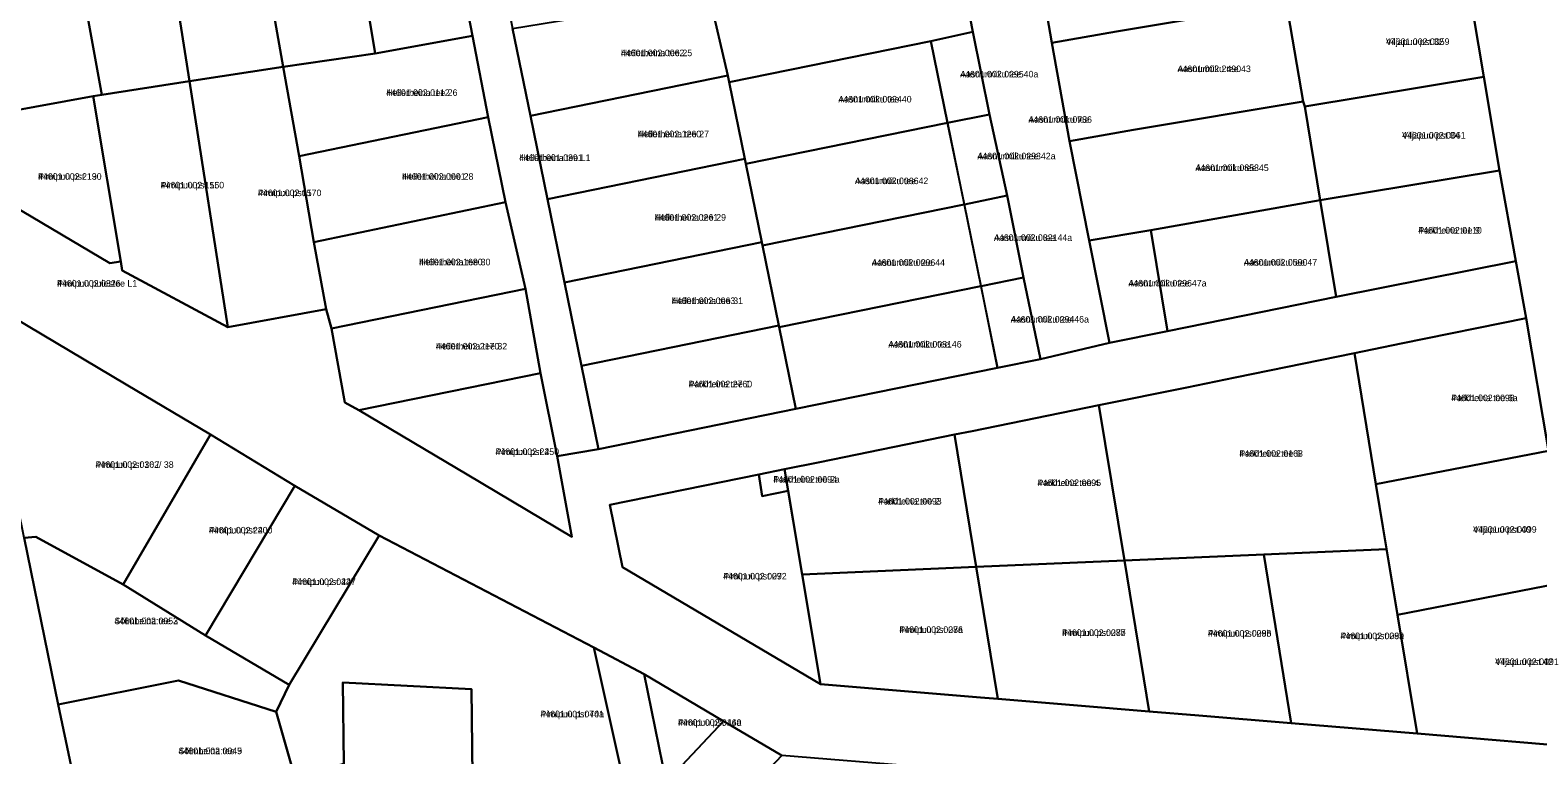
# Model space of a CAD drawing. Extents: x 551843 to 558501, y 6589003 to 6595718.
# Drawn here: x 552845.1 to 553189.3, y 6593581.9 to 6593747.5 of the extents above; entities that cross this region are included whole.
import ezdxf

# ---------------------------------------------------------------- set-up
doc = ezdxf.new("R2010")
doc.units = 0
for name, color, linetype in [('L_AADRESS', 7, 'Continuous'), ('PIIR', 7, 'Continuous'), ('TUNNUS', 7, 'Continuous')]:
    doc.layers.add(name, color=color, linetype=linetype)

msp = doc.modelspace()

# ---------------------------------------------------------------- linework, layer by layer
at = {"layer": 'PIIR'}
for points in [[(553191.73, 6593651.42), (553186.62, 6593681.71), (553184.25, 6593694.72), (553180.55, 6593715.48), (553176.97, 6593736.83), (553173.4, 6593758.18), (553169.77, 6593779.51), (553166.09, 6593800.76), (553162.42, 6593822.28), (553160.89, 6593831), (553157.49, 6593851.43), (553154.18, 6593871.61), (553150.68, 6593891.44), (553147.39, 6593911.24), (553144.11, 6593930.87), (553140.81, 6593950.3)], [(552821.1, 6593719.29), (552863.28, 6593694.26), (552865.76, 6593694.68), (552866.13, 6593692.6), (552890.25, 6593679.67), (552912.68, 6593683.79), (552913.89, 6593679.37), (552916.96, 6593662.41), (552920.11, 6593660.7), (552944.83, 6593645.99), (552968.75, 6593631.76), (552965.39, 6593650.16), (552974.83, 6593651.77), (553019.91, 6593660.97), (553065.96, 6593670.36), (553075.76, 6593672.37), (553091.48, 6593676.07), (553104.77, 6593678.77), (553143.27, 6593686.57), (553184.25, 6593694.72), (553186.62, 6593681.71), (553158.12, 6593675.89), (553147.42, 6593673.71), (553120.17, 6593668.15), (553109.13, 6593665.9), (553089.08, 6593661.81), (553060.14, 6593655.91), (553056.12, 6593655.09), (553025.36, 6593648.81), (553017.3, 6593647.17), (553011.42, 6593645.97), (552977.44, 6593639.05), (552980.33, 6593624.84), (553025.54, 6593598.04), (553062.08, 6593595.02), (553065.98, 6593594.7), (553100.58, 6593591.83), (553111.91, 6593590.89), (553133.02, 6593589.15), (553161.75, 6593586.77), (553203.23, 6593583.33)], [(553192.74, 6593452.2), (553183, 6593451.01), (553180.86, 6593470.76), (553180.39, 6593474.73), (553178.04, 6593494.42), (553175.68, 6593514.18), (553173.33, 6593533.94), (553170.99, 6593553.7), (553169.16, 6593569.08), (553125.23, 6593572.96), (553114.25, 6593573.79), (553109.25, 6593574.21), (553078.12, 6593576.72), (553048.42, 6593579.15), (553016.67, 6593581.78), (553003.41, 6593589.62), (552985.27, 6593600.37), (552973.75, 6593606.43), (552924.75, 6593632.08), (552905.53, 6593643.36), (552886.26, 6593655.11), (552867, 6593666.54), (552838.18, 6593683.65)], [(552843.75, 6593631.48), (552851.49, 6593593.45), (552857.43, 6593565.28), (552858.98, 6593557.89), (552893.85, 6593537.25), (552930.37, 6593515.29), (552934.05, 6593515.82), (552938.2, 6593516.55), (552929.12, 6593505.81), (552906.21, 6593519.15), (552886.22, 6593531.15), (552866.16, 6593543), (552846.1, 6593554.84), (552826.04, 6593566.7)]]:
    msp.add_lwpolyline(points, dxfattribs=at)
for points in [[(553078.32, 6593744.64), (553082.38, 6593722.14), (553086.88, 6593699.44), (553091.48, 6593676.07), (553075.76, 6593672.37), (553071.91, 6593691.03), (553068.13, 6593709.71), (553064.09, 6593728.25), (553060.34, 6593747.13), (553056.95, 6593764.34), (553061.78, 6593765.12), (553054.53, 6593804.21), (553062.99, 6593805.67), (553070.41, 6593766.62), (553074.44, 6593767.17)], [(552938.66, 6593784.79), (552947.28, 6593786.88), (552955.24, 6593747.91), (552959.33, 6593727.95), (552963.21, 6593708.91), (552967.09, 6593689.85), (552970.95, 6593670.81), (552974.83, 6593651.77), (552965.39, 6593650.16), (552961.64, 6593669.12), (552958.18, 6593688.4), (552953.65, 6593708.18), (552949.64, 6593727.61), (552946.09, 6593746.24)], [(552917.35, 6593781.79), (552938.66, 6593784.79), (552946.09, 6593746.24), (552923.88, 6593742.21)], [(552917.35, 6593781.79), (552923.88, 6593742.21), (552902.85, 6593739.16), (552895.95, 6593778.5)], [(552895.95, 6593778.5), (552902.85, 6593739.16), (552881.48, 6593735.82), (552875.31, 6593775.13)], [(553089.22, 6593769.74), (553108.36, 6593773.1), (553127.96, 6593776.37), (553128.7, 6593772.79), (553131.9, 6593753.71), (553093.11, 6593747.18), (553078.32, 6593744.64), (553074.44, 6593767.17)], [(552875.31, 6593775.13), (552881.48, 6593735.82), (552861.42, 6593732.71), (552854.39, 6593771.71)], [(552854.39, 6593771.71), (552861.42, 6593732.71), (552859.5, 6593732.41), (552839.93, 6593728.82), (552833.44, 6593768.29)], [(553018.55, 6593758.14), (553039.93, 6593761.6), (553047.12, 6593762.76), (553056.95, 6593764.34), (553060.34, 6593747.13), (553050.74, 6593745.02), (553004.68, 6593735.61), (553004.38, 6593737.14), (553000.19, 6593755.19)], [(553173.4, 6593758.18), (553176.97, 6593736.83), (553136.08, 6593730.09), (553135.71, 6593731.2), (553132.31, 6593751.28)], [(553004.38, 6593737.14), (552959.33, 6593727.95), (552955.24, 6593747.91), (552975.79, 6593751.26), (552997.18, 6593754.69), (553000.19, 6593755.19)], [(553082.38, 6593722.14), (553078.32, 6593744.64), (553093.11, 6593747.18), (553131.9, 6593753.71), (553132.31, 6593751.28), (553135.71, 6593731.2), (553096.99, 6593724.71)], [(552949.64, 6593727.61), (552906.48, 6593718.75), (552902.85, 6593739.16), (552923.88, 6593742.21), (552946.09, 6593746.24)], [(553050.74, 6593745.02), (553060.34, 6593747.13), (553064.09, 6593728.25), (553054.56, 6593726.36)], [(553054.55, 6593726.36), (553008.48, 6593716.95), (553008.25, 6593718.1), (553004.68, 6593735.61), (553050.74, 6593745.02)], [(552902.85, 6593739.16), (552906.48, 6593718.75), (552909.85, 6593699.06), (552912.68, 6593683.79), (552890.25, 6593679.67), (552881.48, 6593735.82)], [(552861.42, 6593732.71), (552881.48, 6593735.82), (552890.25, 6593679.67), (552866.13, 6593692.6), (552865.76, 6593694.68), (552859.5, 6593732.41)], [(552959.33, 6593727.95), (553004.38, 6593737.14), (553004.68, 6593735.61), (553008.25, 6593718.1), (552963.21, 6593708.91)], [(553176.97, 6593736.83), (553180.55, 6593715.48), (553139.64, 6593708.64), (553136.08, 6593730.09)], [(552821.1, 6593719.29), (552819.79, 6593725.53), (552839.93, 6593728.82), (552859.5, 6593732.41), (552865.76, 6593694.68), (552863.28, 6593694.26)], [(553054.56, 6593726.36), (553064.09, 6593728.25), (553068.13, 6593709.71), (553058.38, 6593707.68)], [(553086.88, 6593699.44), (553082.38, 6593722.14), (553096.99, 6593724.71), (553135.71, 6593731.2), (553136.08, 6593730.09), (553139.64, 6593708.64), (553100.92, 6593701.82)], [(552906.48, 6593718.75), (552949.64, 6593727.61), (552953.65, 6593708.18), (552909.85, 6593699.06)], [(553054.55, 6593726.36), (553058.35, 6593707.7), (553012.3, 6593698.3), (553012.13, 6593699.06), (553008.48, 6593716.95)], [(552967.09, 6593689.85), (552963.21, 6593708.91), (553008.25, 6593718.1), (553008.48, 6593716.95), (553012.13, 6593699.06)], [(553180.55, 6593715.48), (553184.25, 6593694.72), (553143.27, 6593686.57), (553139.64, 6593708.64)], [(552958.18, 6593688.4), (552913.89, 6593679.37), (552912.68, 6593683.79), (552909.85, 6593699.06), (552953.65, 6593708.18)], [(553058.35, 6593707.7), (553062.16, 6593689.04), (553016.11, 6593679.64), (553016.03, 6593680.03), (553012.3, 6593698.3)], [(553058.38, 6593707.68), (553068.13, 6593709.71), (553071.91, 6593691.03), (553062.18, 6593689.02)], [(553104.77, 6593678.77), (553100.92, 6593701.82), (553139.64, 6593708.64), (553143.27, 6593686.57)], [(553086.88, 6593699.44), (553100.92, 6593701.82), (553104.77, 6593678.77), (553091.48, 6593676.07)], [(553012.13, 6593699.06), (553012.3, 6593698.3), (553016.03, 6593680.03), (552970.95, 6593670.81), (552967.09, 6593689.85)], [(553062.18, 6593689.02), (553071.91, 6593691.03), (553075.76, 6593672.37), (553065.96, 6593670.36)], [(552916.96, 6593662.41), (552913.89, 6593679.37), (552958.18, 6593688.4), (552961.64, 6593669.12), (552920.11, 6593660.7)], [(553016.11, 6593679.64), (553062.16, 6593689.04), (553065.96, 6593670.36), (553019.91, 6593660.97)], [(552838.18, 6593683.65), (552867, 6593666.54), (552886.26, 6593655.11), (552866.29, 6593620.87), (552846.42, 6593631.76), (552843.75, 6593631.48), (552833.76, 6593680.47)], [(553016.03, 6593680.03), (553016.11, 6593679.64), (553019.91, 6593660.97), (552974.83, 6593651.77), (552970.95, 6593670.81)], [(553158.12, 6593675.89), (553186.62, 6593681.71), (553191.73, 6593651.42), (553152.34, 6593643.76), (553147.42, 6593673.71)], [(553089.08, 6593661.81), (553109.13, 6593665.9), (553120.17, 6593668.15), (553147.42, 6593673.71), (553152.34, 6593643.76), (553154.77, 6593628.96), (553126.74, 6593627.74), (553094.91, 6593626.35)], [(552965.39, 6593650.16), (552968.75, 6593631.76), (552944.83, 6593645.99), (552920.11, 6593660.7), (552961.64, 6593669.12)], [(553060.14, 6593655.91), (553089.08, 6593661.81), (553094.91, 6593626.35), (553061.05, 6593624.88), (553056.12, 6593655.09)], [(552905.53, 6593643.36), (552885.11, 6593609.17), (552866.29, 6593620.87), (552886.26, 6593655.11)], [(553025.36, 6593648.81), (553056.12, 6593655.09), (553061.05, 6593624.88), (553021.32, 6593623.15), (553017.3, 6593647.17)], [(553191.73, 6593651.42), (553196.62, 6593622.46), (553196.77, 6593621.59), (553157.24, 6593613.91), (553152.34, 6593643.76)], [(553011.42, 6593645.97), (553012.24, 6593641.04), (553018.12, 6593642.24), (553021.32, 6593623.15), (553025.54, 6593598.04), (552980.33, 6593624.84), (552977.44, 6593639.05)], [(553017.3, 6593647.17), (553018.12, 6593642.24), (553012.24, 6593641.04), (553011.42, 6593645.97)], [(552905.53, 6593643.36), (552924.75, 6593632.08), (552904.22, 6593597.92), (552885.11, 6593609.17)], [(552846.42, 6593631.76), (552866.29, 6593620.87), (552885.11, 6593609.17), (552904.22, 6593597.92), (552901.22, 6593591.79), (552878.99, 6593598.88), (552851.49, 6593593.45), (552843.75, 6593631.48)], [(552924.75, 6593632.08), (552973.75, 6593606.43), (552982.46, 6593567.41), (552964.95, 6593548.93), (552954.73, 6593558.93), (552946.29, 6593557.27), (552945.82, 6593596.9), (552916.45, 6593598.49), (552916.72, 6593579.88), (552905.55, 6593576.81), (552901.22, 6593591.79), (552904.22, 6593597.92)], [(553154.77, 6593628.96), (553157.24, 6593613.91), (553161.75, 6593586.77), (553133.02, 6593589.15), (553126.74, 6593627.74)], [(553061.05, 6593624.88), (553065.98, 6593594.7), (553062.08, 6593595.02), (553025.54, 6593598.04), (553021.32, 6593623.15)], [(553094.91, 6593626.35), (553100.58, 6593591.83), (553065.98, 6593594.7), (553061.05, 6593624.88)], [(553126.74, 6593627.74), (553133.02, 6593589.15), (553111.91, 6593590.89), (553100.58, 6593591.83), (553094.91, 6593626.35)], [(553196.77, 6593621.59), (553203.23, 6593583.33), (553161.75, 6593586.77), (553157.24, 6593613.91)], [(553003.41, 6593589.62), (553016.67, 6593581.78), (552993.98, 6593557.72), (552985.76, 6593550.93), (552982.46, 6593567.41), (552973.75, 6593606.43), (552985.27, 6593600.37), (552990.29, 6593575.7)], [(552851.49, 6593593.45), (552878.99, 6593598.88), (552901.22, 6593591.79), (552905.55, 6593576.81), (552891.93, 6593571.94), (552857.43, 6593565.28)], [(552917.33, 6593551.59), (552916.93, 6593565.53), (552916.72, 6593579.88), (552916.45, 6593598.49), (552945.82, 6593596.9), (552946.29, 6593557.27), (552927.8, 6593553.63)], [(553003.41, 6593589.62), (552990.29, 6593575.7), (552985.27, 6593600.37)]]:
    msp.add_lwpolyline(points, close=True, dxfattribs=at)

# ---------------------------------------------------------------- texts
at = {"layer": 'L_AADRESS'}
for s, p in [('Viljapuu pst 32', (553154.63, 6593744.13)), ('Hellerheina tee 25', (552979.95, 6593741.57)), ('Aasnurmiku tee 43', (553107.05, 6593737.93)), ('Aasnurmiku tee 40a', (553057.42, 6593736.71)), ('Hellerheina tee 26', (552926.37, 6593732.49)), ('Aasnurmiku tee 40', (553029.61, 6593730.99)), ('Aasnurmiku tee', (553073, 6593726.35)), ('Hellerheina tee 27', (552983.79, 6593723.03)), ('Viljapuu pst 34', (553158.32, 6593722.74)), ('Hellerheina tee L1', (552956.74, 6593717.62)), ('Aasnurmiku tee 42a', (553061.35, 6593718)), ('Pirnipuu pst 13', (552846.9, 6593713.33)), ('Hellerheina tee 28', (552930, 6593713.33)), ('Aasnurmiku tee 45', (553111.13, 6593715.32)), ('Pirnipuu pst 15', (552874.88, 6593711.35)), ('Pirnipuu pst 17', (552897.08, 6593709.59)), ('Aasnurmiku tee 42', (553033.41, 6593712.33)), ('Hellerheina tee 29', (552987.67, 6593703.98)), ('Aasnurmiku tee 44a', (553065.14, 6593699.36)), ('Parkheina tee 9', (553162.01, 6593701.03)), ('Hellerheina tee 30', (552933.89, 6593693.78)), ('Aasnurmiku tee 44', (553037.23, 6593693.67)), ('Aasnurmiku tee 47', (553122.19, 6593693.71)), ('Pirnipuu puiestee L1', (552851.24, 6593688.91)), ('Aasnurmiku tee 47a', (553095.83, 6593688.95)), ('Hellerheina tee 31', (552991.56, 6593684.93)), ('Aasnurmiku tee 46a', (553068.97, 6593680.7)), ('Aasnurmiku tee 46', (553041.03, 6593675)), ('Hellerheina tee 32', (552937.71, 6593674.55)), ('Parkheina tee 1', (552995.43, 6593665.9)), ('Parkheina tee 6a', (553169.52, 6593662.74)), ('Pirnipuu pst 36 // 38', (552860.01, 6593647.5)), ('Pirnipuu pst 25', (552951.34, 6593650.44)), ('Parkheina tee 6', (553121.16, 6593650.03)), ('Parkheina tee 2a', (553014.77, 6593644.11)), ('Parkheina tee 4', (553075.08, 6593643.34)), ('Parkheina tee 2', (553038.69, 6593639.12)), ('Pirnipuu pst 40', (552885.91, 6593632.51)), ('Viljapuu pst 40', (553174.53, 6593632.67)), ('Pirnipuu pst 42', (552904.93, 6593620.73)), ('Pirnipuu pst 27', (553003.31, 6593622)), ('Sõlmheina tee 3', (552864.34, 6593611.78)), ('Pirnipuu pst 27a', (553043.54, 6593609.79)), ('Pirnipuu pst 27b', (553080.69, 6593609.09)), ('Pirnipuu pst 29b', (553113.96, 6593608.95)), ('Pirnipuu pst 29a', (553144.25, 6593608.36)), ('Viljapuu pst 42', (553179.57, 6593602.46)), ('Pirnipuu pst 44a', (552961.6, 6593590.5)), ('Pirnipuu pst 46a', (552992.99, 6593588.56)), ('Sõlmheina tee 5', (552878.96, 6593582.08))]:
    msp.add_text(s, height=1.5, dxfattribs=at).set_placement(p)
at = {"layer": 'TUNNUS'}
for s, p in [('44601:002:0059', (553154.63, 6593744.13)), ('44601:002:0062', (552979.95, 6593741.57)), ('44601:002:2490', (553107.05, 6593737.93)), ('44601:002:0295', (553057.42, 6593736.71)), ('44601:002:0112', (552926.37, 6593732.49)), ('44601:002:0024', (553029.61, 6593730.99)), ('44601:001:0736', (553073, 6593726.35)), ('44601:002:1260', (552983.79, 6593723.03)), ('44601:002:0061', (553158.32, 6593722.74)), ('44601:001:0391', (552956.74, 6593717.62)), ('44601:002:0293', (553061.35, 6593718)), ('44601:002:2190', (552846.9, 6593713.33)), ('44601:002:0001', (552930, 6593713.33)), ('44601:001:0853', (553111.13, 6593715.32)), ('44601:002:1560', (552874.88, 6593711.35)), ('44601:002:1570', (552897.08, 6593709.59)), ('44601:002:0066', (553033.41, 6593712.33)), ('44601:002:0261', (552987.67, 6593703.98)), ('44601:002:0321', (553065.14, 6593699.36)), ('44601:002:0110', (553162.01, 6593701.03)), ('44601:002:1680', (552933.89, 6593693.78)), ('44601:002:0206', (553037.23, 6593693.67)), ('44601:002:0500', (553122.19, 6593693.71)), ('44601:002:0326', (552851.24, 6593688.91)), ('44601:002:0296', (553095.83, 6593688.95)), ('44601:002:0063', (552991.56, 6593684.93)), ('44601:002:0294', (553068.97, 6593680.7)), ('44601:002:0031', (553041.03, 6593675)), ('44601:002:2170', (552937.71, 6593674.55)), ('44601:002:2760', (552995.43, 6593665.9)), ('44601:002:0098', (553169.52, 6593662.74)), ('44601:002:0102', (552860.01, 6593647.5)), ('44601:002:2450', (552951.34, 6593650.44)), ('44601:002:0168', (553121.16, 6593650.03)), ('44601:002:0094', (553014.77, 6593644.11)), ('44601:002:0095', (553075.08, 6593643.34)), ('44601:002:0093', (553038.69, 6593639.12)), ('44601:002:2200', (552885.91, 6593632.51)), ('44601:002:0099', (553174.53, 6593632.67)), ('44601:002:0247', (552904.93, 6593620.73)), ('44601:002:0092', (553003.31, 6593622)), ('44601:002:0052', (552864.34, 6593611.78)), ('44601:002:0086', (553043.54, 6593609.79)), ('44601:002:0087', (553080.69, 6593609.09)), ('44601:002:0088', (553113.96, 6593608.95)), ('44601:002:0089', (553144.25, 6593608.36)), ('44601:002:0091', (553179.57, 6593602.46)), ('44601:001:0701', (552961.6, 6593590.5)), ('44601:002:0140', (552992.99, 6593588.56)), ('44601:002:0049', (552878.96, 6593582.08))]:
    msp.add_text(s, height=1.5, dxfattribs=at).set_placement(p)

doc.saveas('drawing.dxf')
